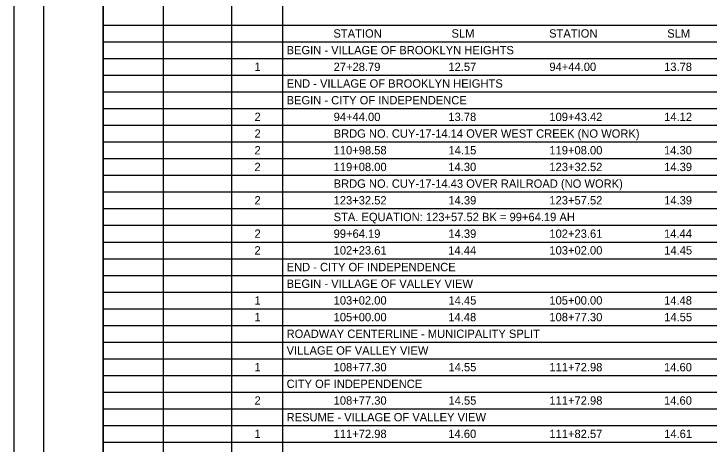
# Model space of a CAD drawing. Extents: x 768 to 809.1, y -451.7 to -422.6.
# Drawn here: x 771.57 to 783.25, y -437.06 to -429.84 of the extents above; entities that cross this region are included whole.
import ezdxf

# ---------------------------------------------------------------- set-up
doc = ezdxf.new("R2010")
doc.units = 0
for name, color, linetype in [('Level 11', 7, 'Continuous'), ('SH_Border', 7, 'Continuous'), ('SH_Cut_Line', 7, 'Continuous')]:
    doc.layers.add(name, color=color, linetype=linetype)

msp = doc.modelspace()

# ---------------------------------------------------------------- linework, layer by layer
at = {"layer": 'Level 11'}
for p, q in [((773.069, -426.67), (773.069, -447.67)), ((774.073, -426.67), (774.073, -445.71)), ((775.226, -426.67), (775.226, -445.71)), ((776.083, -426.67), (776.083, -445.71)), ((773.069, -430.03), (803.094, -430.03)), ((773.069, -430.31), (803.094, -430.31)), ((773.069, -430.59), (803.094, -430.59)), ((773.069, -430.87), (803.094, -430.87)), ((773.069, -431.15), (803.094, -431.15)), ((773.069, -431.43), (803.094, -431.43)), ((773.069, -431.71), (803.094, -431.71)), ((773.069, -431.99), (803.094, -431.99)), ((773.069, -432.27), (803.094, -432.27)), ((773.069, -432.55), (803.094, -432.55)), ((773.069, -432.83), (803.094, -432.83)), ((773.069, -433.11), (803.094, -433.11)), ((773.069, -433.39), (803.094, -433.39)), ((773.069, -433.67), (803.094, -433.67)), ((773.069, -433.95), (803.094, -433.95)), ((773.069, -434.23), (803.094, -434.23)), ((773.069, -434.51), (803.094, -434.51)), ((773.069, -434.79), (803.094, -434.79)), ((773.069, -435.07), (803.094, -435.07)), ((773.069, -435.35), (803.094, -435.35)), ((773.069, -435.63), (803.094, -435.63)), ((773.069, -435.91), (803.094, -435.91)), ((773.069, -436.19), (803.094, -436.19)), ((773.069, -436.47), (803.094, -436.47)), ((773.069, -436.75), (803.094, -436.75)), ((773.069, -437.03), (803.094, -437.03))]:
    msp.add_line(p, q, dxfattribs=at)
at = {"layer": 'SH_Border'}
for points in [[(772.069, -426.67), (773.069, -426.67), (773.069, -447.67), (772.069, -447.67)], [(773.069, -426.67), (805.069, -426.67), (805.069, -447.67), (773.069, -447.67)]]:
    msp.add_lwpolyline(points, close=True, dxfattribs=at)
at = {"layer": 'SH_Cut_Line'}
msp.add_lwpolyline([(771.569, -448.17), (805.569, -448.17), (805.569, -426.17), (771.569, -426.17)], close=True, dxfattribs=at)

# ---------------------------------------------------------------- texts
at = {"layer": 'Level 11'}
for s, p in [('STATION', (776.936, -430.24)), ('SLM', (778.92, -430.24)), ('STATION', (780.559, -430.24)), ('SLM', (782.543, -430.24)), ('BEGIN - VILLAGE OF BROOKLYN HEIGHTS', (776.149, -430.52)), ('1', (775.609, -430.8)), ('27+28.79', (776.939, -430.8)), ('12.57', (778.867, -430.8)), ('94+44.00', (780.563, -430.8)), ('13.78', (782.49, -430.8)), ('END - VILLAGE OF BROOKLYN HEIGHTS', (776.149, -431.08)), ('BEGIN - CITY OF INDEPENDENCE', (776.149, -431.36)), ('2', (775.61, -431.64)), ('94+44.00', (776.939, -431.64)), ('13.78', (778.866, -431.64)), ('109+43.42', (780.563, -431.64)), ('14.12', (782.491, -431.64)), ('2', (775.61, -431.92)), ('BRDG NO. CUY-17-14.14 OVER WEST CREEK (NO WORK)', (776.939, -431.92)), ('2', (775.61, -432.2)), ('110+98.58', (776.939, -432.2)), ('14.15', (778.868, -432.2)), ('119+08.00', (780.563, -432.2)), ('14.30', (782.489, -432.2)), ('2', (775.61, -432.48)), ('119+08.00', (776.939, -432.48)), ('14.30', (778.866, -432.48)), ('123+32.52', (780.563, -432.48)), ('14.39', (782.491, -432.48)), ('BRDG NO. CUY-17-14.43 OVER RAILROAD (NO WORK)', (776.939, -432.76)), ('2', (775.61, -433.04)), ('123+32.52', (776.939, -433.04)), ('14.39', (778.867, -433.04)), ('123+57.52', (780.563, -433.04)), ('14.39', (782.491, -433.04)), ('STA. EQUATION: 123+57.52 BK = 99+64.19 AH', (776.939, -433.32)), ('2', (775.61, -433.6)), ('99+64.19', (776.939, -433.6)), ('14.39', (778.867, -433.6)), ('102+23.61', (780.563, -433.6)), ('14.44', (782.489, -433.6)), ('2', (775.61, -433.88)), ('102+23.61', (776.939, -433.88)), ('14.44', (778.865, -433.88)), ('103+02.00', (780.563, -433.88)), ('14.45', (782.492, -433.88)), ('END - CITY OF INDEPENDENCE', (776.149, -434.16)), ('BEGIN - VILLAGE OF VALLEY VIEW', (776.149, -434.44)), ('1', (775.609, -434.72)), ('103+02.00', (776.939, -434.72)), ('14.45', (778.868, -434.72)), ('105+00.00', (780.563, -434.72)), ('14.48', (782.49, -434.72)), ('1', (775.609, -435)), ('105+00.00', (776.939, -435)), ('14.48', (778.866, -435)), ('108+77.30', (780.563, -435)), ('14.55', (782.492, -435)), ('ROADWAY CENTERLINE - MUNICIPALITY SPLIT', (776.149, -435.28)), ('VILLAGE OF VALLEY VIEW', (776.149, -435.56)), ('1', (775.609, -435.84)), ('108+77.30', (776.939, -435.84)), ('14.55', (778.868, -435.84)), ('111+72.98', (780.563, -435.84)), ('14.60', (782.489, -435.84)), ('CITY OF INDEPENDENCE', (776.149, -436.12)), ('2', (775.61, -436.4)), ('108+77.30', (776.939, -436.4)), ('14.55', (778.868, -436.4)), ('111+72.98', (780.563, -436.4)), ('14.60', (782.489, -436.4)), ('RESUME - VILLAGE OF VALLEY VIEW', (776.149, -436.68)), ('1', (775.609, -436.96)), ('111+72.98', (776.939, -436.96)), ('14.60', (778.866, -436.96)), ('111+82.57', (780.563, -436.96)), ('14.61', (782.491, -436.96))]:
    msp.add_text(s, height=0.14, dxfattribs=at).set_placement(p)

doc.saveas('drawing.dxf')
